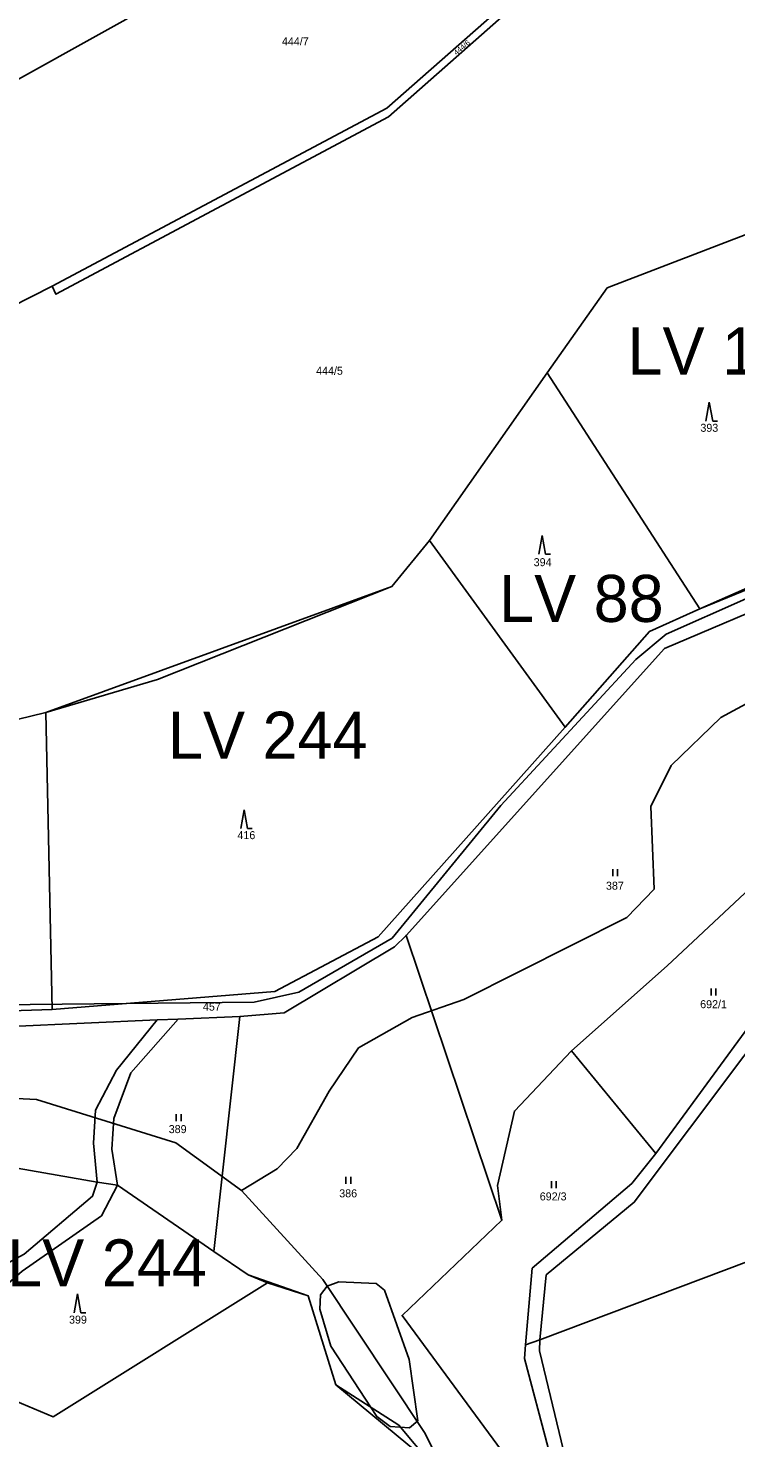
# Model space of a CAD drawing. Extents: x -590606 to -587796, y -1065936 to -1062515.
# Drawn here: x -590130 to -589979.7, y -1064835.5 to -1064536.2 of the extents above; entities that cross this region are included whole.
import ezdxf

# ---------------------------------------------------------------- set-up
doc = ezdxf.new("R2010")
doc.units = 0
for name, color, linetype in [('Cesty', 7, 'Continuous'), ('Lesy', 7, 'Continuous'), ('Parcela nároku', 7, 'Continuous'), ('Plocha pro ocenění', 7, 'Continuous'), ('Tok', 7, 'Continuous'), ('Vrstva 30', 7, 'Continuous'), ('Čísla LV', 7, 'Continuous')]:
    doc.layers.add(name, color=color, linetype=linetype)

msp = doc.modelspace()

# ---------------------------------------------------------------- linework, layer by layer
at = {"layer": 'Cesty'}
msp.add_lwpolyline([(-589947.72, -1064513.59), (-589949.88, -1064540.92), (-589950.43, -1064547.89), (-589948.41, -1064569.06), (-589947.59, -1064617.66), (-589957.04, -1064650.23), (-589977.62, -1064657.4), (-589994.52, -1064664.89), (-590000.93, -1064670.22), (-590029.62, -1064701.27), (-590052.7, -1064729.41), (-590072.54, -1064740.91), (-590082.04, -1064743), (-590136.41, -1064743.6)], dxfattribs=at)
at = {"layer": 'Lesy'}
msp.add_line((-590044.76, -1064645), (-590015.95, -1064684.62), dxfattribs=at)
for points in [[(-590019.81, -1064609.39), (-590003.6, -1064634.43), (-589987.38, -1064659.47)], [(-590178.93, -1064808.3), (-590153.03, -1064819.2), (-590124.7, -1064831.07), (-590079.14, -1064802.65)]]:
    msp.add_lwpolyline(points, dxfattribs=at)
at = {"layer": 'Parcela nároku'}
for points in [[(-590181.91, -1064373.1), (-590156.28, -1064378.4), (-590124.79, -1064490.26), (-590109.28, -1064534.33), (-590138.48, -1064550.51), (-590151.83, -1064503.77), (-590164.28, -1064447.03)], [(-590109.28, -1064534.33), (-590138.48, -1064550.51), (-590167.49, -1064566.1), (-590192.88, -1064580.25), (-590207.57, -1064588.44), (-590186.83, -1064622.39), (-590124.92, -1064590.99), (-590053.84, -1064553.16), (-590005.01, -1064510.14), (-589938.63, -1064437.29), (-589884.45, -1064391.22), (-589885.98, -1064387.45), (-589929.34, -1064390.39), (-589956.3, -1064412.36), (-589982.87, -1064435.99), (-590007.42, -1064458.77), (-590028.57, -1064482.51), (-590040.8, -1064494.15), (-590053.24, -1064502.26), (-590080.15, -1064517.38)], [(-589880.45, -1064400.57), (-589883.7, -1064393.06), (-589937.59, -1064438.88), (-590003.8, -1064511.09), (-590053.49, -1064555.03), (-590124.11, -1064592.68), (-590124.92, -1064590.99), (-590186.83, -1064622.39), (-590180.83, -1064633.16), (-590150.37, -1064687.39), (-590126.23, -1064681.5), (-590102.55, -1064674.49), (-590052.75, -1064654.76), (-590044.76, -1064645), (-590019.81, -1064609.39), (-590007.04, -1064591.31), (-589963.4, -1064574.51), (-589977.74, -1064526.91), (-589976.91, -1064516.68), (-589967.81, -1064501.82), (-589959.93, -1064493.53), (-589948.84, -1064472.81), (-589924.19, -1064439.77), (-589897.81, -1064414.93)], [(-589883.7, -1064393.06), (-589884.45, -1064391.22), (-589938.63, -1064437.29), (-590005.01, -1064510.14), (-590053.84, -1064553.16), (-590124.92, -1064590.99), (-590124.11, -1064592.68), (-590053.49, -1064555.03), (-590003.8, -1064511.09), (-589937.59, -1064438.88)], [(-589958.96, -1064614.81), (-589960.29, -1064573.39), (-589963.4, -1064574.51), (-590007.04, -1064591.31), (-590019.81, -1064609.39), (-589987.38, -1064659.47), (-589971.3, -1064652.42), (-589964.01, -1064636.55)], [(-590019.81, -1064609.39), (-589987.38, -1064659.47), (-589998.08, -1064664.3), (-590015.95, -1064684.62), (-590044.76, -1064645)], [(-590052.75, -1064654.76), (-590102.55, -1064674.49), (-590126.23, -1064681.5), (-590124.93, -1064744.61), (-590077.63, -1064740.78), (-590055.66, -1064729.15), (-590015.95, -1064684.62), (-590044.76, -1064645)], [(-590029.38, -1064789.34), (-590030.32, -1064781.93), (-590026.74, -1064766.14), (-590014.61, -1064753.36), (-589994.33, -1064735.3), (-589955.82, -1064699.26), (-589933.74, -1064676.94), (-589954.36, -1064652.15), (-589967.17, -1064656.15), (-589994.87, -1064667.89), (-590049.73, -1064728.85)], [(-589955.82, -1064699.26), (-589933.74, -1064676.94), (-589929.38, -1064685.74), (-589915.44, -1064713.86), (-589918.67, -1064718.62), (-589935.64, -1064722.32), (-589950.4, -1064722.88), (-589967.67, -1064735.51), (-589996.74, -1064775.17), (-590014.61, -1064753.36), (-589994.33, -1064735.3)], [(-590124.93, -1064744.61), (-590126.23, -1064681.5), (-590150.37, -1064687.39), (-590138.87, -1064720.46), (-590181.82, -1064746.41)], [(-589933.73, -1064728.16), (-589950.22, -1064726.99), (-589966.31, -1064738.85), (-590001.3, -1064785.51), (-590019.97, -1064800.95), (-590021.33, -1064814.7), (-589976.81, -1064797.92), (-589940.65, -1064780.54)], [(-590085.05, -1064746.07), (-590075.63, -1064745.31), (-590052.18, -1064731.26), (-590049.73, -1064728.85), (-590029.38, -1064789.34), (-590050.58, -1064809.55), (-590029.51, -1064838.25), (-590038.82, -1064839.84), (-590044.4, -1064841.09), (-590051.27, -1064832.84), (-590064.68, -1064824.28), (-590070.56, -1064805.35), (-590079.14, -1064802.65), (-590083.28, -1064800.94), (-590090.57, -1064795.95)], [(-590108.2, -1064758), (-590111.79, -1064767.7), (-590112.26, -1064774.23), (-590111.01, -1064781.85), (-590090.57, -1064795.95), (-590085.05, -1064746.07), (-590098.16, -1064746.6)], [(-590180.2, -1064750.31), (-590218.45, -1064757.35), (-590223.63, -1064769.81), (-590206.17, -1064767.1), (-590193.65, -1064765.23), (-590171.72, -1064770.28), (-590159.33, -1064769.87), (-590162.33, -1064773.04), (-590115.36, -1064781.23), (-590116.14, -1064772.93), (-590115.67, -1064765.99), (-590111.21, -1064757.48), (-590102.62, -1064746.78)], [(-589879.87, -1064753.99), (-589868.03, -1064748.13), (-589866.87, -1064751.2), (-589721.04, -1064765.62), (-589732.48, -1064773.33), (-589781.14, -1064797.6), (-589848.05, -1064822.46), (-589965.99, -1064862.62), (-590008.01, -1064872.65), (-590021.45, -1064817.05), (-590021.33, -1064814.7), (-589976.81, -1064797.92), (-589940.65, -1064780.54)], [(-590050.58, -1064809.55), (-590029.38, -1064789.34), (-590030.32, -1064781.93), (-590026.74, -1064766.14), (-590014.61, -1064753.36), (-589996.74, -1064775.17), (-590001.82, -1064781.5), (-590022.96, -1064799.52), (-590024.4, -1064815.82), (-590024.63, -1064818.7), (-590019.58, -1064837.67), (-590029.51, -1064838.25)], [(-590162.33, -1064773.04), (-590194.13, -1064801.81), (-590182.15, -1064806.89), (-590171.52, -1064802.67), (-590159.53, -1064800.38), (-590134.88, -1064798.75), (-590130.88, -1064796.51), (-590116.36, -1064784.23), (-590115.36, -1064781.23)], [(-590090.57, -1064795.95), (-590083.28, -1064800.94), (-590079.14, -1064802.65), (-590124.7, -1064831.07), (-590153.03, -1064819.2), (-590131.29, -1064800.13), (-590114.42, -1064788.38), (-590111.01, -1064781.85)], [(-590182.24, -1064846.33), (-590153.03, -1064819.2), (-590124.7, -1064831.07), (-590079.14, -1064802.65), (-590070.56, -1064805.35), (-590064.68, -1064824.28), (-590051.27, -1064832.84), (-590044.4, -1064841.09), (-590102.75, -1064858.29), (-590106.62, -1064860.16), (-590127.95, -1064871.98), (-590132.38, -1064869.89)]]:
    msp.add_lwpolyline(points, close=True, dxfattribs=at)
for points in [[(-590181.82, -1064746.41), (-590124.93, -1064744.61), (-590077.63, -1064740.78), (-590055.66, -1064729.15), (-590015.95, -1064684.62), (-589998.08, -1064664.3), (-589987.38, -1064659.47), (-589971.3, -1064652.42), (-589959.2, -1064647.94), (-589946.23, -1064647.93), (-589916.03, -1064650.62), (-589914.7, -1064653.41), (-589954.36, -1064652.15), (-589967.17, -1064656.15), (-589994.87, -1064667.89), (-590049.73, -1064728.85), (-590052.18, -1064731.26), (-590075.63, -1064745.31), (-590085.05, -1064746.07), (-590098.16, -1064746.6), (-590102.62, -1064746.78), (-590180.2, -1064750.31)], [(-589967.67, -1064735.51), (-589996.74, -1064775.17), (-590001.82, -1064781.5), (-590022.96, -1064799.52), (-590024.4, -1064815.82), (-590021.33, -1064814.7), (-590019.97, -1064800.95), (-590001.3, -1064785.51), (-589966.31, -1064738.85)], [(-590130.88, -1064796.51), (-590116.36, -1064784.23), (-590115.36, -1064781.23), (-590116.14, -1064772.93), (-590115.67, -1064765.99), (-590111.21, -1064757.48), (-590102.62, -1064746.78), (-590098.16, -1064746.6), (-590108.2, -1064758), (-590111.79, -1064767.7), (-590112.26, -1064774.23), (-590111.01, -1064781.85), (-590114.42, -1064788.38), (-590131.29, -1064800.13)], [(-590019.58, -1064837.67), (-590024.63, -1064818.7), (-590024.4, -1064815.82), (-590021.33, -1064814.7), (-590021.45, -1064817.05), (-590008.01, -1064872.65)]]:
    msp.add_lwpolyline(points, dxfattribs=at)
at = {"layer": 'Plocha pro ocenění'}
for points in [[(-590150.37, -1064687.39), (-590126.23, -1064681.5), (-590052.75, -1064654.76), (-590044.76, -1064645), (-590019.81, -1064609.39), (-590007.04, -1064591.31), (-589963.4, -1064574.51), (-589960.29, -1064573.39), (-589949.66, -1064571.06), (-589945.2, -1064570.03), (-589931.51, -1064618.95), (-589922.06, -1064639.58), (-589916.03, -1064650.62), (-589946.23, -1064647.93), (-589959.2, -1064647.94), (-589987.38, -1064659.47), (-589998.08, -1064664.3), (-590015.95, -1064684.62), (-590055.66, -1064729.15), (-590077.63, -1064740.78), (-590124.93, -1064744.61), (-590181.82, -1064746.41)], [(-590162.33, -1064773.04), (-590115.36, -1064781.23), (-590111.01, -1064781.85), (-590090.57, -1064795.95), (-590083.28, -1064800.94), (-590070.56, -1064805.35), (-590064.68, -1064824.28), (-590044.4, -1064841.09), (-590029.51, -1064838.25), (-590019.58, -1064837.67), (-590015.37, -1064859.51), (-590013.23, -1064888.37), (-590009.44, -1064904.18), (-590007.09, -1064950.34), (-590014.04, -1064956.28), (-590016.56, -1064971.44), (-590016.47, -1064995), (-590048.46, -1065083.71)]]:
    msp.add_lwpolyline(points, dxfattribs=at)
at = {"layer": 'Tok'}
for points in [[(-590084.72, -1064783.05), (-590077.11, -1064778.41), (-590072.98, -1064774.07), (-590066.09, -1064761.92), (-590059.84, -1064752.71), (-590048.45, -1064746.26), (-590037.45, -1064742.42), (-590002.84, -1064725.01), (-589997.1, -1064719.03), (-589997.81, -1064701.47), (-589993.45, -1064692.75), (-589982.91, -1064682.57), (-589965.22, -1064673), (-589940.27, -1064663.42), (-589926.34, -1064660.64), (-589913.01, -1064662.58), (-589903.32, -1064662.68), (-589880.13, -1064666.14), (-589859.37, -1064667.18), (-589848.22, -1064668.7)], [(-590438.41, -1064819.57), (-590435.96, -1064818.69), (-590427.03, -1064816.54), (-590407.51, -1064812.59), (-590381.07, -1064804.84), (-590326.05, -1064786.37), (-590308.1, -1064778.43), (-590294.28, -1064774.37), (-590288.67, -1064773.61), (-590271.08, -1064781.17), (-590259.53, -1064781.6), (-590246.44, -1064780.74), (-590213.85, -1064774.68), (-590162.37, -1064761.96), (-590128.21, -1064763.66), (-590098.65, -1064772.87), (-590084.72, -1064783.05), (-590067.4, -1064801.95), (-590045.87, -1064834.39), (-590030.83, -1064863.75), (-590022.45, -1064892.28), (-590020.72, -1064920.32), (-590022.17, -1064941.23)]]:
    msp.add_lwpolyline(points, dxfattribs=at)
msp.add_lwpolyline([(-590066.5, -1064803.3), (-590064.04, -1064802.41), (-590056.09, -1064802.76), (-590054.35, -1064804.19), (-590049.07, -1064818.93), (-590047.27, -1064831.94), (-590049, -1064833.4), (-590053.15, -1064833.12), (-590055.99, -1064831.04), (-590065.75, -1064816.09), (-590068.03, -1064808.19), (-590067.89, -1064805.15)], close=True, dxfattribs=at)
at = {"layer": 'Vrstva 30'}
for p, q in [((-589985.36, -1064615.63), (-589986.09, -1064619.63)), ((-589985.36, -1064615.63), (-589984.63, -1064619.63)), ((-589984.63, -1064619.63), (-589983.63, -1064619.63)), ((-590020.84, -1064643.88), (-590021.58, -1064647.88)), ((-590020.84, -1064643.88), (-590020.11, -1064647.88)), ((-590020.11, -1064647.88), (-590019.11, -1064647.88)), ((-590084.13, -1064702.14), (-590084.86, -1064706.14)), ((-590084.13, -1064702.14), (-590083.4, -1064706.14)), ((-590083.4, -1064706.14), (-590082.4, -1064706.14)), ((-590005.86, -1064714.78), (-590005.86, -1064716.28)), ((-590004.83, -1064716.28), (-590004.83, -1064714.78)), ((-589984.98, -1064740.12), (-589984.98, -1064741.62)), ((-589983.95, -1064741.62), (-589983.95, -1064740.12)), ((-590098.56, -1064766.81), (-590098.56, -1064768.31)), ((-590097.54, -1064768.31), (-590097.54, -1064766.81)), ((-590062.53, -1064780.12), (-590062.53, -1064781.62)), ((-590061.51, -1064781.62), (-590061.51, -1064780.12)), ((-590018.89, -1064781), (-590018.89, -1064782.5)), ((-590017.86, -1064782.5), (-590017.86, -1064781)), ((-590119.51, -1064804.97), (-590120.24, -1064808.97)), ((-590119.51, -1064804.97), (-590118.78, -1064808.97)), ((-590118.78, -1064808.97), (-590117.78, -1064808.97))]:
    msp.add_line(p, q, dxfattribs=at)

# ---------------------------------------------------------------- texts
at = {"layer": 'Parcela nároku'}
for s, p in [('444/7', (-590076.11, -1064539.82)), ('444/5', (-590068.85, -1064609.78)), ('393', (-589987.25, -1064621.89)), ('394', (-590022.65, -1064650.43)), ('416', (-590085.56, -1064708.4)), ('387', (-590007.3, -1064719.14)), ('457', (-590092.89, -1064744.82)), ('692/1', (-589987.3, -1064744.3)), ('389', (-590100.15, -1064770.83)), ('386', (-590063.94, -1064784.47)), ('692/3', (-590021.36, -1064785.12)), ('399', (-590121.32, -1064811.29))]:
    msp.add_text(s, height=1.7, dxfattribs=at).set_placement(p)
msp.add_text('444/6', height=1.14, rotation=40.3944, dxfattribs=at).set_placement((-590039.04, -1064541.99))
at = {"layer": 'Čísla LV'}
for s, p in [('LV 10', (-590002.72, -1064609.74)), ('LV 88', (-590029.99, -1064662.28)), ('LV 244', (-590100.31, -1064691.34)), ('LV 244', (-590134.45, -1064803.4))]:
    msp.add_text(s, height=10, dxfattribs=at).set_placement(p)

doc.saveas('drawing.dxf')
